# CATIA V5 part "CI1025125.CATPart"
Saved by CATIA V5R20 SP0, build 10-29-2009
Part number: CI1025125
Bounding box of the stored display mesh (mm): x -24 to 24, y -20.11 to 159.5, z -26.352 to 28.386
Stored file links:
  C:\Users\Raffaele\Desktop\3D X SITO CF\BOLEX\19-INCLINED ASSEMBLY REF_CI\CI1025125.CATPart
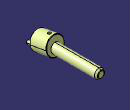
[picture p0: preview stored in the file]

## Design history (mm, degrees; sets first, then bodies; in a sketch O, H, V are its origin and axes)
Set1
  DatumSurface1 to DatumSurface16 "MANIFOLD_SOLID_BREP #389"
  DatumSurface17 to DatumSurface39 "MANIFOLD_SOLID_BREP #1134"
Body1 (main body)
